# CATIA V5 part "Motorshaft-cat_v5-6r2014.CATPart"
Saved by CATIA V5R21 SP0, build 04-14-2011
Part number: Motorshaft
Bounding box of the stored display mesh (mm): x -18.415 to 18.415, y -304.8 to 304.8, z -18.228 to 18.228
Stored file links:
  D:\CATIA V5R21 E-RESOURCES\CATIA-V5R21\catia-v5r21-Tut\c12-catia-v5r21-tut\c12-catia-v5r21-tut01\Motorshaft-cat_v5r21.CATPart
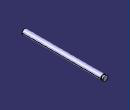
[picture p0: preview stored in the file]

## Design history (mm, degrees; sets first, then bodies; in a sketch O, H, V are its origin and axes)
Body1 (main body)
  Sketch1 on zx-plane, origin (0, 0, 0), H (-1, 0, 0), V (0, 0, 1)
    circle A1 centre (0, 0) radius 18.415
    radius A1 = 18.415
  Pad1: profile Sketch1, direction (0, 1, 0), length 304.8, mirrored extent
  Sketch2 on yz-plane, origin (0, 0, 0), H (0, 1, 0), V (0, 0, 1)
    line L1 (287.528, 25.9968) -> (292.1, 25.9968)
    line L2 (292.1, 25.9968) -> (292.1, 15.24)
    line L3 (292.1, 15.24) -> (287.528, 15.24)
    line L4 (287.528, 15.24) -> (287.528, 25.9968)
    reference projected line E1 (304.8, -18.415) -> (304.8, 18.415) from edge of Pad1
    distance E1 L2 = 12.7
    distance H L3 = 15.24
    length L1 = 4.572
    horizontal: L1 H, L3 H
    vertical: L2 V, L4 V
  Groove1: profile Sketch2, axis axis of face of Pad1, angle 360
